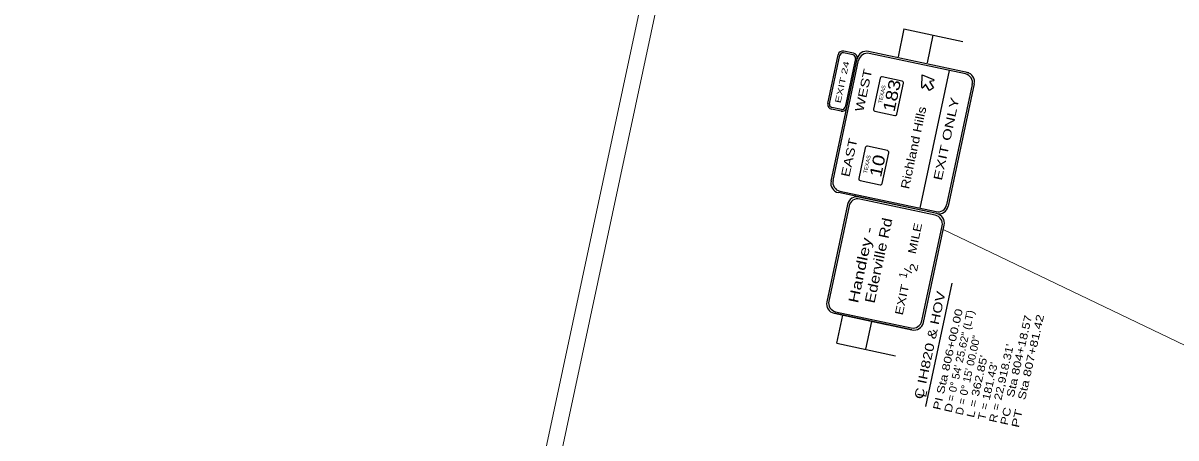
# Model space of a CAD drawing. Extents: x 2363411 to 2369702, y 6977197 to 6988655.
# Drawn here: x 2363411 to 2365218, y 6981800 to 6982449 of the extents above; entities that cross this region are included whole.
import ezdxf
from ezdxf.enums import TextEntityAlignment as Align

# ---------------------------------------------------------------- set-up
doc = ezdxf.new("R2010")
doc.units = 0
doc.header["$LTSCALE"] = 5.6
for name, color, linetype, lineweight in [('1', 7, 'Continuous', 25), ('10', 7, 'Continuous', 13), ('61', 7, 'Continuous', 25)]:
    doc.layers.add(name, color=color, linetype=linetype, lineweight=lineweight)
doc.layers.add('28', color=7, linetype='Continuous')
doc.layers.add('33', color=7, linetype='Continuous')

msp = doc.modelspace()

# ---------------------------------------------------------------- linework, layer by layer
at = {"layer": '1'}
for p, q in [((2364791.441, 6982439.764), (2364782.23, 6982396.363)), ((2364791.441, 6982439.764), (2364883.425, 6982420.242)), ((2364836.827, 6982430.132), (2364827.615, 6982386.73)), ((2364672.039, 6982323.148), (2364688.334, 6982399.437)), ((2364674.786, 6982322.56), (2364691.081, 6982398.847)), ((2364711.759, 6982399.219), (2364696.646, 6982402.448)), ((2364712.348, 6982401.974), (2364697.233, 6982405.202)), ((2364715.367, 6982393.656), (2364699.062, 6982317.375)), ((2364893.25, 6982370.971), (2364735.899, 6982404.592)), ((2364887.669, 6982369.294), (2364737.153, 6982401.458)), ((2364677.167, 6982201.46), (2364718.115, 6982393.07)), ((2364680.293, 6982202.705), (2364720.444, 6982390.652)), ((2364754.023, 6982362.614), (2364743.735, 6982314.48)), ((2364788.59, 6982358.108), (2364757.358, 6982364.788)), ((2364816.632, 6982159.186), (2364862.655, 6982374.637)), ((2364837.811, 6982358.771), (2364832.408, 6982357.518)), ((2364780.453, 6982306.631), (2364790.742, 6982354.772)), ((2364824.535, 6982352.422), (2364821.206, 6982348.015)), ((2364831.299, 6982343.68), (2364825.664, 6982352.383)), ((2364898.474, 6982352.602), (2364858.321, 6982164.662)), ((2364901.609, 6982353.848), (2364860.675, 6982162.239)), ((2364692.91, 6982311.014), (2364677.804, 6982314.249)), ((2364693.498, 6982313.769), (2364678.392, 6982316.998)), ((2364745.894, 6982311.137), (2364777.118, 6982304.471)), ((2364730.817, 6982253.927), (2364720.536, 6982205.785)), ((2364765.398, 6982249.438), (2364734.15, 6982256.102)), ((2364757.262, 6982197.936), (2364767.543, 6982246.085)), ((2364722.687, 6982202.449), (2364753.92, 6982195.777)), ((2364842.877, 6982150.714), (2364688.691, 6982183.662)), ((2364691.112, 6982186.021), (2364841.631, 6982153.842)), ((2364703.058, 6982165.242), (2364670.467, 6982012.673)), ((2364705.419, 6982162.82), (2364673.601, 6982013.92)), ((2364842.87, 6982150.7), (2364720.856, 6982176.772)), ((2364840.455, 6982148.348), (2364722.109, 6982173.632)), ((2364819.458, 6981982.763), (2364851.275, 6982131.656)), ((2364821.817, 6981980.341), (2364854.409, 6982132.894)), ((2364684.421, 6981997.228), (2364802.759, 6981971.944)), ((2364681.999, 6981994.868), (2364804.012, 6981968.802)), ((2364686.419, 6981948.248), (2364695.75, 6981991.624)), ((2364731.779, 6981938.491), (2364741.108, 6981981.867)), ((2364686.419, 6981948.248), (2364778.349, 6981928.474))]:
    msp.add_line(p, q, dxfattribs=at)
at = {"layer": '1', "lineweight": 13}
msp.add_line((2365420.991, 6981854), (2364852.9, 6982125.825), dxfattribs=at)
at = {"layer": '1'}
for points in [[(2364819.399, 6982348.704), (2364820.132, 6982367.862), (2364837.921, 6982360.708)], [(2364832.003, 6982356.494), (2364837.652, 6982347.776), (2364834.483, 6982345.74), (2364831.299, 6982343.68)], [(2364804.012, 6981968.802), (2364681.999, 6981994.868), (2364764.287, 6981977.291)]]:
    msp.add_lwpolyline(points, dxfattribs=at)
for centre, radius, start, end in [((2364695.67, 6982397.866), 7.501, 77.93922, 167.93922), ((2364695.67, 6982397.866), 4.688, 77.93922, 167.93922), ((2364710.78, 6982394.637), 4.688, 347.93922, 77.93922), ((2364710.78, 6982394.637), 7.501, 347.93922, 77.93922), ((2364732.775, 6982389.93), 15.001, 77.93586, 167.93586), ((2364734.216, 6982387.704), 14.063, 77.93586, 167.93586), ((2364756.77, 6982362.04), 2.813, 77.93476, 167.93476), ((2364787.997, 6982355.365), 2.813, 347.93476, 77.93476), ((2364832.553, 6982356.88), 0.675, 102.95656, 212.93966), ((2364837.563, 6982359.757), 1.012, 282.82003, 68.20117), ((2364884.733, 6982355.538), 14.063, 347.93586, 77.93586), ((2364886.959, 6982356.98), 15.001, 347.93586, 77.93586), ((2364820.401, 6982348.638), 1.012, 177.67816, 323.05929), ((2364825.075, 6982352.035), 0.675, 32.93966, 142.92277), ((2364679.371, 6982321.581), 7.501, 167.93922, 257.93922), ((2364679.371, 6982321.581), 4.688, 167.93922, 257.93922), ((2364694.481, 6982318.352), 7.501, 257.93922, 347.93922), ((2364694.481, 6982318.352), 4.688, 257.93922, 347.93922), ((2364746.477, 6982313.888), 2.813, 167.93476, 257.93476), ((2364777.704, 6982307.213), 2.813, 257.93476, 347.93476), ((2364733.57, 6982253.35), 2.813, 77.93586, 167.93586), ((2364764.798, 6982246.676), 2.813, 347.93586, 77.93586), ((2364691.827, 6982198.327), 15.001, 167.93528, 257.93528), ((2364694.052, 6982199.769), 14.063, 167.93528, 257.93528), ((2364723.279, 6982205.198), 2.813, 167.93586, 257.93586), ((2364754.506, 6982198.524), 2.813, 257.93586, 347.93586), ((2364717.728, 6982162.104), 15.001, 77.93966, 167.93966), ((2364719.17, 6982159.878), 14.063, 77.93966, 167.93966), ((2364844.569, 6982167.602), 14.063, 257.93528, 347.93528), ((2364846.011, 6982165.376), 15.001, 257.93528, 347.93528), ((2364837.517, 6982134.593), 14.063, 347.93966, 77.93966), ((2364839.742, 6982136.035), 15.001, 347.93966, 77.93966), ((2364685.132, 6982009.54), 15.001, 167.93966, 257.93966), ((2364687.357, 6982010.982), 14.063, 167.93966, 257.93966), ((2364805.704, 6981985.696), 14.063, 257.93966, 347.93966), ((2364807.146, 6981983.471), 15.001, 257.93966, 347.93966)]:
    msp.add_arc(centre, radius, start, end, dxfattribs=at)
at = {"layer": '10'}
for p, q in [((2363411.416, 6977949.748), (2365605.51, 6988218.434)), ((2363435.864, 6977944.524), (2365629.958, 6988213.21))]:
    msp.add_line(p, q, dxfattribs=at)
at = {"layer": '61'}
msp.add_line((2364825.64, 6981849.036), (2364866.874, 6982042.015), dxfattribs=at)

# ---------------------------------------------------------------- texts
at = {"layer": '1'}
for s, height, rotation, width, p in [('EXIT 24', 9.188, 77.939, 1.5, (2364699.091, 6982355.561)), ('WEST', 13.5, 77.935, 1.3, (2364734.726, 6982342.431)), ('EXIT ONLY', 13.5, 77.94, 1.4, (2364864.408, 6982266.308)), ('Richland Hills', 13.5, 77.935, 1.2, (2364813.016, 6982252.557)), ('EAST', 13.5, 77.935, 1.3, (2364712.236, 6982237.186)), ('Ederville Rd', 15.68, 77.94, 1.2, (2364759.322, 6982075.858)), ('Handley -', 15.68, 77.94, 1.35, (2364732.088, 6982068.969)), ('MILE', 12.54, 77.94, 1.25, (2364814.939, 6982110.7)), ('2', 12.54, 77.94, 1.3, (2364812.941, 6982065.16)), ('1', 12.54, 77.94, 0.95, (2364796.162, 6982053.311)), ('/', 12.54, 77.94, 1.3, (2364804.121, 6982060.042)), ('EXIT', 12.54, 77.94, 1.3, (2364794.444, 6982014.766))]:
    msp.add_text(s, height=height, rotation=rotation, dxfattribs=dict(at, width=width)).set_placement(p, align=Align.CENTER)
for s, height, rotation, width, p in [('183', 18.75, 77.935, 1.2, (2364776.451, 6982308.973)), ('TEXAS', 6, 77.935, 1.1, (2364756.855, 6982322.76)), ('TEXAS', 6, 77.936, 1.1, (2364733.449, 6982213.138)), ('10', 18.75, 77.936, 1.25, (2364755.442, 6982206.532))]:
    msp.add_text(s, height=height, rotation=rotation, dxfattribs=dict(at, width=width)).set_placement(p)
at = {"layer": '28', "width": 1.3}
msp.add_text('C IH820 & HOV', height=14, rotation=78.048, dxfattribs=at).set_placement((2364838.855, 6981943.458), align=Align.CENTER)
at = {"layer": '33'}
for s, width, p in [('PI Sta 806+00.00', 1.3, (2364848.333, 6981842.522)), ('= 0° 54\' 25.62" (LT)', 1.05, (2364869.83, 6981856.142)), ('Sta 804+18.57', 1.25, (2364963.407, 6981862.453)), ('Sta 807+81.42', 1.3, (2364981.233, 6981858.45)), ('D = 0° 15\' 00.00"', 1.05, (2364883.437, 6981834.637)), ("R = 22,918.31'", 1.2, (2364936.096, 6981822.81)), ("L = 362.85'", 1.25, (2364900.99, 6981830.695)), ("T = 181.43'", 1.15, (2364918.543, 6981826.752)), ('D', 1.25, (2364865.886, 6981838.579)), ('PC', 1.25, (2364953.648, 6981818.867)), ('PT', 1.4, (2364971.201, 6981814.925))]:
    msp.add_text(s, height=12, rotation=77.341, dxfattribs=dict(at, width=width)).set_placement(p)
at = {"layer": '61', "width": 1.05}
msp.add_text('L', height=14, rotation=77.939, dxfattribs=at).set_placement((2364827.084, 6981868.03), align=Align.CENTER)

doc.saveas('drawing.dxf')
